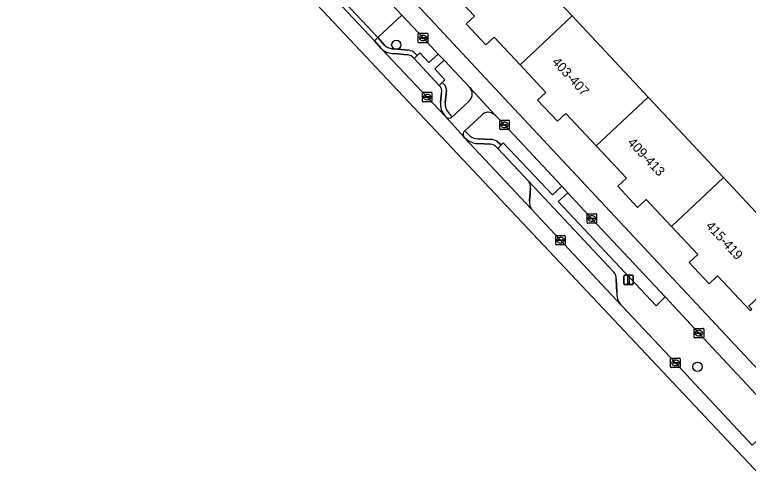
# Model space of a CAD drawing. Extents: x 163147 to 163550, y 380933 to 381639.
# Drawn here: x 163228.3 to 163305.4, y 381059.3 to 381108.1 of the extents above; entities that cross this region are included whole.
import ezdxf

# ---------------------------------------------------------------- set-up
doc = ezdxf.new("R2010")
doc.units = 0
for name, color, linetype in [('IMGEO_Berm_groen', 7, 'Continuous'), ('IMGEO_Berm_open', 7, 'Continuous'), ('IMGEO_Boom', 7, 'Continuous'), ('IMGEO_Erf', 7, 'Continuous'), ('IMGEO_Fietspad_gesloten', 7, 'Continuous'), ('IMGEO_Kolk', 7, 'Continuous'), ('IMGEO_Lichtmast', 7, 'Continuous'), ('IMGEO_Pand', 7, 'Continuous'), ('IMGEO_Pand_nummerreeks', 7, 'Continuous'), ('IMGEO_Parkeervlak_open', 7, 'Continuous'), ('IMGEO_Rijbaan_lokaal_gesloten', 7, 'Continuous'), ('IMGEO_Rijbaan_lokaal_open', 7, 'Continuous'), ('IMGEO_Voetpad_open', 7, 'Continuous')]:
    doc.layers.add(name, color=color, linetype=linetype)

msp = doc.modelspace()

# ---------------------------------------------------------------- linework, layer by layer
at = {"layer": 'IMGEO_Berm_groen'}
for points in [[(163271.237, 381105.609), (163268.976, 381108.034), (163266.455, 381105.68), (163267.166, 381104.887)], [(163270.245, 381104.151), (163270.603, 381103.802), (163270.861, 381104.066), (163271.81, 381103.049), (163272.803, 381103.944), (163271.237, 381105.609)], [(163267.93, 381104.507), (163268.195, 381104.493), (163269.587, 381104.37)], [(163276.249, 381100.24), (163276.112, 381100.428), (163273.414, 381103.291), (163272.436, 381102.374), (163273.489, 381101.219), (163273.21, 381100.945), (163273.56, 381100.588)], [(163273.677, 381100.123), (163273.637, 381099.775), (163273.532, 381098.817)], [(163273.924, 381097.725), (163274.261, 381097.355), (163276.058, 381098.995)], [(163277.337, 381097.489), (163275.595, 381095.866), (163276.119, 381095.337)], [(163279.786, 381096.484), (163278.746, 381097.539)], [(163279.045, 381094.724), (163279.411, 381094.383), (163279.622, 381094.61), (163284.805, 381089.129), (163285.784, 381090.039), (163279.786, 381096.484)], [(163277.009, 381095.017), (163278.322, 381094.966)]]:
    msp.add_lwpolyline(points, dxfattribs=at)
msp.add_lwpolyline([(163289, 381086.592), (163286.426, 381089.355), (163285.416, 381088.445), (163295.704, 381077.473), (163296.653, 381078.396)], close=True, dxfattribs=at)
for centre, radius, start, end in [((163268.141, 381105.89), 1.399, 225.79564, 261.31449), ((163269.477, 381102.941), 1.433, 57.58938, 85.59298), ((163272.416, 381100.053), 1.263, 3.17703, 25.06934), ((163275.362, 381099.739), 1.018, 313.07706, 29.47903), ((163274.911, 381098.696), 1.384, 174.96991, 224.52376), ((163278.065, 381096.865), 0.958, 44.66922, 139.39549), ((163277.068, 381096.578), 1.562, 232.60264, 267.84521), ((163278.247, 381093.54), 1.428, 56.01455, 86.97297)]:
    msp.add_arc(centre, radius, start, end, dxfattribs=at)
at = {"layer": 'IMGEO_Berm_open'}
for points in [[(163267.166, 381104.887), (163266.455, 381105.68), (163266.09, 381105.339), (163266.816, 381104.528)], [(163269.587, 381104.37), (163268.195, 381104.493), (163267.93, 381104.507)], [(163268.16, 381103.994), (163269.524, 381103.874)], [(163270.276, 381103.467), (163270.603, 381103.802), (163270.245, 381104.151)], [(163273.56, 381100.588), (163273.21, 381100.945), (163272.901, 381100.641)], [(163273.532, 381098.817), (163273.637, 381099.775), (163273.677, 381100.123)], [(163273.143, 381099.856), (163273.032, 381098.845)], [(163274.232, 381097.329), (163274.261, 381097.355), (163273.924, 381097.725)], [(163273.501, 381097.445), (163273.604, 381097.334)], [(163276.119, 381095.337), (163275.595, 381095.866), (163275.589, 381095.861)], [(163275.466, 381095.274), (163275.582, 381095.146)], [(163278.322, 381094.966), (163277.009, 381095.017)], [(163278.97, 381094.126), (163279.071, 381094.019), (163279.411, 381094.383), (163279.045, 381094.724)], [(163276.969, 381094.518), (163278.283, 381094.467)]]:
    msp.add_lwpolyline(points, dxfattribs=at)
for centre, radius, start, end in [((163268.141, 381105.89), 1.399, 225.79564, 261.31449), ((163268.106, 381105.817), 1.824, 224.97069, 271.69134), ((163269.44, 381102.821), 1.056, 37.70291, 85.45052), ((163269.477, 381102.941), 1.433, 57.58938, 85.59298), ((163272.451, 381100.073), 0.725, 342.60834, 51.65866), ((163272.416, 381100.053), 1.263, 3.17703, 25.06934), ((163274.891, 381098.689), 1.866, 175.21281, 221.82889), ((163274.911, 381098.696), 1.384, 174.96991, 224.52376), ((163273.921, 381097.654), 0.45, 225.34455, 313.74311), ((163275.842, 381095.502), 0.44, 125.18331, 211.14762), ((163277.068, 381096.578), 1.562, 232.60264, 267.84521), ((163277.063, 381096.572), 2.056, 223.91049, 267.36978), ((163278.247, 381093.54), 1.428, 56.01455, 86.97297), ((163278.253, 381093.544), 0.923, 39.0617, 88.14228)]:
    msp.add_arc(centre, radius, start, end, dxfattribs=at)
at = {"layer": 'IMGEO_Boom'}
for centre in [(163268.394, 381104.913), (163300.068, 381071.051)]:
    msp.add_circle(centre, 0.489, dxfattribs=at)
at = {"layer": 'IMGEO_Erf'}
msp.add_lwpolyline([(163327.566, 381099.224), (163294.213, 381134.916), (163292.456, 381133.038), (163277.888, 381117.465), (163278.299, 381116.877), (163278.43, 381116.999), (163281.846, 381113.348), (163286.891, 381107.954), (163294.88, 381099.413), (163302.803, 381090.943), (163307.632, 381085.78)], dxfattribs=at)
at = {"layer": 'IMGEO_Fietspad_gesloten'}
for points in [[(163431.634, 380936.983), (163426.381, 380942.59), (163389.734, 380981.756), (163386.168, 380985.564), (163372.648, 381000), (163319.829, 381056.397), (163310.14, 381066.773), (163306.558, 381070.608), (163278.278, 381100.892), (163188.415, 381197.241)], [(163236.873, 381142.447), (163243.701, 381135.131), (163244.35, 381134.436), (163254.641, 381123.403), (163255.277, 381122.722), (163262.153, 381115.349), (163268.976, 381108.034), (163271.237, 381105.609), (163272.803, 381103.944), (163273.414, 381103.291), (163276.112, 381100.428), (163276.249, 381100.24), (163278.746, 381097.539), (163279.786, 381096.484), (163285.784, 381090.039), (163286.426, 381089.355), (163289, 381086.592), (163296.653, 381078.396), (163300.254, 381074.541), (163308.689, 381065.5)]]:
    msp.add_lwpolyline(points, dxfattribs=at)
at = {"layer": 'IMGEO_Kolk'}
for p, q in [((163270.785, 381106.135), (163271.637, 381106.135)), ((163270.71, 381105.209), (163270.71, 381106.061)), ((163270.969, 381105.629), (163270.969, 381105.641)), ((163271.407, 381105.592), (163271.009, 381105.592)), ((163271.012, 381105.678), (163271.41, 381105.678)), ((163271.221, 381105.355), (163271.196, 381105.355)), ((163271.198, 381105.915), (163271.223, 381105.915)), ((163271.453, 381105.641), (163271.453, 381105.629)), ((163271.711, 381106.061), (163271.711, 381105.209)), ((163271.637, 381105.135), (163270.785, 381105.135)), ((163271.218, 381099.923), (163272.07, 381099.923)), ((163271.143, 381098.997), (163271.143, 381099.849)), ((163271.402, 381099.417), (163271.402, 381099.429)), ((163271.84, 381099.38), (163271.442, 381099.38)), ((163271.445, 381099.466), (163271.843, 381099.466)), ((163271.631, 381099.703), (163271.656, 381099.703)), ((163271.886, 381099.429), (163271.886, 381099.417)), ((163272.144, 381099.849), (163272.144, 381098.997)), ((163272.07, 381098.923), (163271.218, 381098.923)), ((163271.654, 381099.143), (163271.629, 381099.143)), ((163279.275, 381096.066), (163279.275, 381096.918)), ((163279.35, 381096.992), (163280.202, 381096.992)), ((163280.276, 381096.918), (163280.276, 381096.066)), ((163279.534, 381096.486), (163279.534, 381096.498)), ((163279.972, 381096.449), (163279.574, 381096.449)), ((163279.577, 381096.535), (163279.975, 381096.535)), ((163279.786, 381096.212), (163279.761, 381096.212)), ((163279.763, 381096.772), (163279.788, 381096.772)), ((163280.018, 381096.498), (163280.018, 381096.486)), ((163280.202, 381095.992), (163279.35, 381095.992)), ((163288.451, 381086.215), (163288.451, 381087.067)), ((163288.526, 381087.141), (163289.378, 381087.141)), ((163288.939, 381086.921), (163288.964, 381086.921)), ((163289.452, 381087.067), (163289.452, 381086.215)), ((163289.378, 381086.141), (163288.526, 381086.141)), ((163288.71, 381086.635), (163288.71, 381086.647)), ((163289.148, 381086.598), (163288.75, 381086.598)), ((163288.753, 381086.684), (163289.151, 381086.684)), ((163288.962, 381086.361), (163288.937, 381086.361)), ((163289.194, 381086.647), (163289.194, 381086.635)), ((163285.157, 381083.941), (163285.157, 381084.793)), ((163285.232, 381084.867), (163286.084, 381084.867)), ((163285.645, 381084.647), (163285.67, 381084.647)), ((163286.158, 381084.793), (163286.158, 381083.941)), ((163286.084, 381083.867), (163285.232, 381083.867)), ((163285.416, 381084.361), (163285.416, 381084.373)), ((163285.854, 381084.324), (163285.456, 381084.324)), ((163285.459, 381084.41), (163285.857, 381084.41)), ((163285.668, 381084.087), (163285.643, 381084.087)), ((163285.9, 381084.373), (163285.9, 381084.361)), ((163299.711, 381074.158), (163299.711, 381075.01)), ((163299.786, 381075.084), (163300.638, 381075.084)), ((163299.97, 381074.578), (163299.97, 381074.59)), ((163300.408, 381074.541), (163300.01, 381074.541)), ((163300.013, 381074.627), (163300.411, 381074.627)), ((163300.199, 381074.864), (163300.224, 381074.864)), ((163300.454, 381074.59), (163300.454, 381074.578)), ((163300.712, 381075.01), (163300.712, 381074.158)), ((163300.638, 381074.084), (163299.786, 381074.084)), ((163300.222, 381074.304), (163300.197, 381074.304)), ((163297.236, 381071.035), (163297.236, 381071.887)), ((163297.311, 381071.961), (163298.163, 381071.961)), ((163297.495, 381071.455), (163297.495, 381071.467)), ((163297.933, 381071.418), (163297.535, 381071.418)), ((163297.538, 381071.504), (163297.936, 381071.504)), ((163297.724, 381071.741), (163297.749, 381071.741)), ((163297.979, 381071.467), (163297.979, 381071.455)), ((163298.237, 381071.887), (163298.237, 381071.035)), ((163298.163, 381070.961), (163297.311, 381070.961)), ((163297.747, 381071.181), (163297.722, 381071.181))]:
    msp.add_line(p, q, dxfattribs=at)
for points in [[(163270.785, 381106.135), (163271.637, 381106.135)], [(163270.71, 381105.209), (163270.71, 381106.061)], [(163271.711, 381106.061), (163271.711, 381105.209)], [(163271.637, 381105.135), (163270.785, 381105.135)], [(163271.218, 381099.923), (163272.07, 381099.923)], [(163271.143, 381098.997), (163271.143, 381099.849)], [(163272.144, 381099.849), (163272.144, 381098.997)], [(163272.07, 381098.923), (163271.218, 381098.923)], [(163279.275, 381096.066), (163279.275, 381096.918)], [(163279.35, 381096.992), (163280.202, 381096.992)], [(163280.276, 381096.918), (163280.276, 381096.066)], [(163280.202, 381095.992), (163279.35, 381095.992)], [(163288.451, 381086.215), (163288.451, 381087.067)], [(163288.526, 381087.141), (163289.378, 381087.141)], [(163289.452, 381087.067), (163289.452, 381086.215)], [(163289.378, 381086.141), (163288.526, 381086.141)], [(163285.157, 381083.941), (163285.157, 381084.793)], [(163285.232, 381084.867), (163286.084, 381084.867)], [(163286.158, 381084.793), (163286.158, 381083.941)], [(163286.084, 381083.867), (163285.232, 381083.867)], [(163299.711, 381074.158), (163299.711, 381075.01)], [(163299.786, 381075.084), (163300.638, 381075.084)], [(163300.712, 381075.01), (163300.712, 381074.158)], [(163300.638, 381074.084), (163299.786, 381074.084)], [(163297.236, 381071.035), (163297.236, 381071.887)], [(163297.311, 381071.961), (163298.163, 381071.961)], [(163298.237, 381071.887), (163298.237, 381071.035)], [(163298.163, 381070.961), (163297.311, 381070.961)]]:
    msp.add_lwpolyline(points, dxfattribs=at)
for centre, radius, start, end in [((163270.787, 381106.059), 0.0765, 91.55205, 178.44795), ((163270.787, 381106.059), 0.0765, 91.55205, 178.44795), ((163271.635, 381106.059), 0.0765, 1.55205, 88.44795), ((163271.635, 381106.059), 0.0765, 1.55205, 88.44795), ((163271.009, 381105.638), 0.0403, 85.87752, 175.75265), ((163271.006, 381105.628), 0.0366, 178.93798, 274.71019), ((163271.41, 381105.635), 0.043, 264.86636, 352.45326), ((163271.414, 381105.64), 0.0386, 1.73085, 96.63898), ((163270.787, 381105.211), 0.0765, 181.55205, 268.44795), ((163270.787, 381105.211), 0.0765, 181.55205, 268.44795), ((163271.635, 381105.211), 0.0765, 271.55205, 358.44795), ((163271.635, 381105.211), 0.0765, 271.55205, 358.44795), ((163271.22, 381099.847), 0.0765, 91.55205, 178.44795), ((163271.22, 381099.847), 0.0765, 91.55205, 178.44795), ((163272.068, 381099.847), 0.0765, 1.55205, 88.44795), ((163272.068, 381099.847), 0.0765, 1.55205, 88.44795), ((163271.442, 381099.426), 0.0403, 85.87752, 175.75265), ((163271.439, 381099.416), 0.0366, 178.93798, 274.71019), ((163271.843, 381099.423), 0.043, 264.86636, 352.45326), ((163271.847, 381099.428), 0.0386, 1.73085, 96.63898), ((163271.22, 381098.999), 0.0765, 181.55205, 268.44795), ((163271.22, 381098.999), 0.0765, 181.55205, 268.44795), ((163272.068, 381098.999), 0.0765, 271.55205, 358.44795), ((163272.068, 381098.999), 0.0765, 271.55205, 358.44795), ((163279.352, 381096.916), 0.0765, 91.55205, 178.44795), ((163279.352, 381096.916), 0.0765, 91.55205, 178.44795), ((163280.2, 381096.916), 0.0765, 1.55205, 88.44795), ((163280.2, 381096.916), 0.0765, 1.55205, 88.44795), ((163279.352, 381096.068), 0.0765, 181.55205, 268.44795), ((163279.352, 381096.068), 0.0765, 181.55205, 268.44795), ((163279.574, 381096.495), 0.0403, 85.87752, 175.75265), ((163279.571, 381096.485), 0.0366, 178.93798, 274.71019), ((163279.975, 381096.492), 0.043, 264.86636, 352.45326), ((163279.979, 381096.497), 0.0386, 1.73085, 96.63898), ((163280.2, 381096.068), 0.0765, 271.55205, 358.44795), ((163280.2, 381096.068), 0.0765, 271.55205, 358.44795), ((163288.528, 381087.065), 0.0765, 91.55205, 178.44795), ((163288.528, 381087.065), 0.0765, 91.55205, 178.44795), ((163289.376, 381087.065), 0.0765, 1.55205, 88.44795), ((163289.376, 381087.065), 0.0765, 1.55205, 88.44795), ((163288.528, 381086.217), 0.0765, 181.55205, 268.44795), ((163288.528, 381086.217), 0.0765, 181.55205, 268.44795), ((163288.75, 381086.644), 0.0403, 85.87752, 175.75265), ((163288.747, 381086.634), 0.0366, 178.93798, 274.71019), ((163289.151, 381086.641), 0.043, 264.86636, 352.45326), ((163289.155, 381086.646), 0.0386, 1.73085, 96.63898), ((163289.376, 381086.217), 0.0765, 271.55205, 358.44795), ((163289.376, 381086.217), 0.0765, 271.55205, 358.44795), ((163285.234, 381084.791), 0.0765, 91.55205, 178.44795), ((163285.234, 381084.791), 0.0765, 91.55205, 178.44795), ((163286.082, 381084.791), 0.0765, 1.55205, 88.44795), ((163286.082, 381084.791), 0.0765, 1.55205, 88.44795), ((163285.234, 381083.943), 0.0765, 181.55205, 268.44795), ((163285.234, 381083.943), 0.0765, 181.55205, 268.44795), ((163285.456, 381084.37), 0.0403, 85.87752, 175.75265), ((163285.453, 381084.36), 0.0366, 178.93798, 274.71019), ((163285.857, 381084.367), 0.043, 264.86636, 352.45326), ((163285.861, 381084.372), 0.0386, 1.73085, 96.63898), ((163286.082, 381083.943), 0.0765, 271.55205, 358.44795), ((163286.082, 381083.943), 0.0765, 271.55205, 358.44795), ((163299.788, 381075.008), 0.0765, 91.55205, 178.44795), ((163299.788, 381075.008), 0.0765, 91.55205, 178.44795), ((163300.01, 381074.587), 0.0403, 85.87752, 175.75265), ((163300.007, 381074.577), 0.0366, 178.93798, 274.71019), ((163300.411, 381074.584), 0.043, 264.86636, 352.45326), ((163300.415, 381074.589), 0.0386, 1.73085, 96.63898), ((163300.636, 381075.008), 0.0765, 1.55205, 88.44795), ((163300.636, 381075.008), 0.0765, 1.55205, 88.44795), ((163299.788, 381074.16), 0.0765, 181.55205, 268.44795), ((163299.788, 381074.16), 0.0765, 181.55205, 268.44795), ((163300.636, 381074.16), 0.0765, 271.55205, 358.44795), ((163300.636, 381074.16), 0.0765, 271.55205, 358.44795), ((163297.313, 381071.885), 0.0765, 91.55205, 178.44795), ((163297.313, 381071.885), 0.0765, 91.55205, 178.44795), ((163297.535, 381071.464), 0.0403, 85.87752, 175.75265), ((163297.532, 381071.454), 0.0366, 178.93798, 274.71019), ((163297.936, 381071.461), 0.043, 264.86636, 352.45326), ((163297.94, 381071.466), 0.0386, 1.73085, 96.63898), ((163298.161, 381071.885), 0.0765, 1.55205, 88.44795), ((163298.161, 381071.885), 0.0765, 1.55205, 88.44795), ((163297.313, 381071.037), 0.0765, 181.55205, 268.44795), ((163297.313, 381071.037), 0.0765, 181.55205, 268.44795), ((163298.161, 381071.037), 0.0765, 271.55205, 358.44795), ((163298.161, 381071.037), 0.0765, 271.55205, 358.44795)]:
    msp.add_arc(centre, radius, start, end, dxfattribs=at)
for centre, major_axis, ratio, start_param, end_param in [((163271.197, 381105.635), (-0.387, 0.002), 0.722429, 4.712389, 7.853982), ((163271.222, 381105.635), (-0.39, 0.002), 0.717154, 1.570796, 4.712389), ((163271.63, 381099.423), (-0.387, 0.002), 0.722429, 4.712389, 7.853982), ((163271.655, 381099.423), (-0.39, 0.002), 0.717154, 1.570796, 4.712389), ((163279.762, 381096.492), (-0.387, 0.002), 0.722429, 4.712389, 7.853982), ((163279.787, 381096.492), (-0.39, 0.002), 0.717154, 1.570796, 4.712389), ((163288.938, 381086.641), (-0.387, 0.002), 0.722429, 4.712389, 7.853982), ((163288.963, 381086.641), (-0.39, 0.002), 0.717154, 1.570796, 4.712389), ((163285.644, 381084.367), (-0.387, 0.002), 0.722429, 4.712389, 7.853982), ((163285.669, 381084.367), (-0.39, 0.002), 0.717154, 1.570796, 4.712389), ((163300.198, 381074.584), (-0.387, 0.002), 0.722429, 4.712389, 7.853982), ((163300.223, 381074.584), (-0.39, 0.002), 0.717154, 1.570796, 4.712389), ((163297.723, 381071.461), (-0.387, 0.002), 0.722429, 4.712389, 7.853982), ((163297.748, 381071.461), (-0.39, 0.002), 0.717154, 1.570796, 4.712389)]:
    msp.add_ellipse(centre, major_axis=major_axis, ratio=ratio, start_param=start_param, end_param=end_param, dxfattribs=at)
at = {"layer": 'IMGEO_Lichtmast'}
for p, q in [((163292.421, 381080.688), (163293.211, 381080.688)), ((163293.211, 381080.688), (163292.421, 381080.688)), ((163292.321, 381079.788), (163292.321, 381080.588)), ((163292.321, 381080.588), (163292.321, 381079.788)), ((163293.311, 381080.588), (163293.311, 381079.788)), ((163293.311, 381079.788), (163293.311, 381080.588)), ((163293.211, 381079.688), (163292.421, 381079.688)), ((163292.421, 381079.688), (163293.211, 381079.688))]:
    msp.add_line(p, q, dxfattribs=at)
msp.add_lwpolyline([(163292.741, 381080.563), (163292.891, 381080.563), (163292.891, 381079.813), (163292.741, 381079.813), (163292.741, 381080.563)], dxfattribs=at)
for centre, start, end in [((163292.421, 381080.588), 90, 180), ((163292.421, 381080.588), 90, 180), ((163293.211, 381080.588), 0, 90), ((163293.211, 381080.588), 360, 90), ((163292.421, 381079.788), 180, 270), ((163292.421, 381079.788), 180, 270), ((163293.211, 381079.788), 270, 0), ((163293.211, 381079.788), 270, 0)]:
    msp.add_arc(centre, 0.1, start, end, dxfattribs=at)
at = {"layer": 'IMGEO_Pand'}
for points in [[(163281.406, 381102.825), (163286.891, 381107.954), (163281.846, 381113.348), (163278.43, 381116.999), (163278.299, 381116.877), (163278.155, 381116.742), (163278.334, 381116.55), (163276.202, 381114.555), (163275.941, 381114.835), (163275.132, 381114.079), (163275.389, 381113.804), (163273.312, 381111.86), (163273.062, 381112.128), (163272.859, 381111.938), (163276.601, 381107.937), (163275.724, 381107.117), (163277.793, 381104.905), (163278.683, 381105.737)], [(163294.88, 381099.413), (163286.891, 381107.954), (163281.406, 381102.825), (163284.13, 381099.913), (163283.255, 381099.095), (163285.338, 381096.869), (163286.218, 381097.692), (163289.402, 381094.288)], [(163297.319, 381085.815), (163302.803, 381090.943), (163294.88, 381099.413), (163289.402, 381094.288), (163292.586, 381090.885), (163291.673, 381090.03), (163293.754, 381087.806), (163294.662, 381088.655)], [(163297.319, 381085.815), (163300.089, 381082.853), (163299.198, 381082.019), (163301.286, 381079.786), (163302.167, 381080.61), (163305.592, 381076.949), (163305.767, 381077.113), (163305.465, 381077.436), (163307.591, 381079.425), (163307.821, 381079.179), (163308.588, 381079.896), (163308.363, 381080.136), (163310.55, 381082.181), (163310.809, 381081.904), (163311.048, 381082.128), (163310.741, 381082.456), (163307.632, 381085.78), (163302.803, 381090.943)]]:
    msp.add_lwpolyline(points, close=True, dxfattribs=at)
at = {"layer": 'IMGEO_Parkeervlak_open'}
for points in [[(163266.816, 381104.528), (163273.501, 381097.445)], [(163269.524, 381103.874), (163268.16, 381103.994)], [(163272.901, 381100.641), (163270.276, 381103.467)], [(163273.032, 381098.845), (163273.143, 381099.856)], [(163275.582, 381095.146), (163282.56, 381087.679)], [(163278.283, 381094.467), (163276.969, 381094.518)], [(163279.071, 381094.019), (163278.97, 381094.126)], [(163282.325, 381090.547), (163279.071, 381094.019)], [(163291.282, 381080.99), (163282.325, 381090.547)], [(163282.52, 381089.792), (163282.393, 381088.49)], [(163282.393, 381088.49), (163282.52, 381089.792)], [(163282.56, 381087.679), (163292.004, 381077.575)], [(163291.567, 381078.881), (163291.528, 381080.259)]]:
    msp.add_lwpolyline(points, dxfattribs=at)
for centre, radius, start, end in [((163268.106, 381105.817), 1.824, 224.97069, 271.69134), ((163269.44, 381102.821), 1.056, 37.70291, 85.45052), ((163272.451, 381100.073), 0.725, 342.60834, 51.65866), ((163274.891, 381098.689), 1.866, 175.21281, 221.82889), ((163277.063, 381096.572), 2.056, 223.91049, 267.36978), ((163278.253, 381093.544), 0.923, 39.0617, 88.14228), ((163281.274, 381089.873), 1.248, 356.28272, 32.68082), ((163281.274, 381089.873), 1.248, 356.28272, 32.68082), ((163283.851, 381088.368), 1.463, 175.20143, 208.06983), ((163283.851, 381088.368), 1.463, 175.20143, 208.06983), ((163290.473, 381080.311), 1.057, 357.19253, 40.00625), ((163293.434, 381078.78), 1.87, 176.89459, 220.10687)]:
    msp.add_arc(centre, radius, start, end, dxfattribs=at)
at = {"layer": 'IMGEO_Rijbaan_lokaal_gesloten'}
for points in [[(163224.239, 381147.157), (163352.566, 381010.865)], [(163305.819, 381062.795), (163299.374, 381069.695), (163297.748, 381071.447), (163292.133, 381077.437), (163292.004, 381077.575), (163282.56, 381087.679), (163275.582, 381095.146), (163275.466, 381095.274), (163273.604, 381097.334), (163273.501, 381097.445), (163266.816, 381104.528), (163266.09, 381105.339), (163259.301, 381112.6), (163257.862, 381114.198), (163229.126, 381144.967)]]:
    msp.add_lwpolyline(points, dxfattribs=at)
at = {"layer": 'IMGEO_Rijbaan_lokaal_open'}
msp.add_lwpolyline([(163268.976, 381108.034), (163262.153, 381115.349), (163259.661, 381112.947), (163266.455, 381105.68)], close=True, dxfattribs=at)
at = {"layer": 'IMGEO_Voetpad_open'}
for points in [[(163188.415, 381197.241), (163278.278, 381100.892), (163306.558, 381070.608)], [(163305.592, 381076.949), (163302.167, 381080.61), (163301.286, 381079.786), (163299.198, 381082.019), (163300.089, 381082.853), (163297.319, 381085.815), (163294.662, 381088.655), (163293.754, 381087.806), (163291.673, 381090.03), (163292.586, 381090.885), (163289.402, 381094.288), (163286.218, 381097.692), (163285.338, 381096.869), (163283.255, 381099.095), (163284.13, 381099.913), (163281.406, 381102.825), (163278.683, 381105.737), (163277.793, 381104.905), (163275.724, 381107.117), (163276.601, 381107.937), (163272.859, 381111.938)], [(163278.746, 381097.539), (163276.249, 381100.24)], [(163276.058, 381098.995), (163274.261, 381097.355), (163274.232, 381097.329)], [(163273.604, 381097.334), (163275.466, 381095.274)], [(163275.589, 381095.861), (163275.595, 381095.866), (163277.337, 381097.489)], [(163285.416, 381088.445), (163286.426, 381089.355), (163285.784, 381090.039), (163284.805, 381089.129), (163279.622, 381094.61), (163279.411, 381094.383), (163279.071, 381094.019), (163282.325, 381090.547), (163291.282, 381080.99)], [(163292.004, 381077.575), (163292.133, 381077.437), (163297.748, 381071.447), (163299.374, 381069.695), (163305.819, 381062.795), (163306.184, 381063.136), (163308.689, 381065.5), (163300.254, 381074.541), (163296.653, 381078.396), (163295.704, 381077.473), (163285.416, 381088.445)], [(163291.528, 381080.259), (163291.567, 381078.881)]]:
    msp.add_lwpolyline(points, dxfattribs=at)
for points in [[(163266.455, 381105.68), (163259.661, 381112.947), (163259.301, 381112.6), (163266.09, 381105.339)], [(163273.414, 381103.291), (163272.803, 381103.944), (163271.81, 381103.049), (163270.861, 381104.066), (163270.603, 381103.802), (163270.276, 381103.467), (163272.901, 381100.641), (163273.21, 381100.945), (163273.489, 381101.219), (163272.436, 381102.374)]]:
    msp.add_lwpolyline(points, close=True, dxfattribs=at)
for centre, radius, start, end in [((163275.362, 381099.739), 1.018, 313.07706, 29.47903), ((163278.065, 381096.865), 0.958, 44.66922, 139.39549), ((163273.921, 381097.654), 0.45, 225.34455, 313.74311), ((163275.842, 381095.502), 0.44, 125.18331, 211.14762), ((163290.473, 381080.311), 1.057, 357.19253, 40.00625), ((163293.434, 381078.78), 1.87, 176.89459, 220.10687)]:
    msp.add_arc(centre, radius, start, end, dxfattribs=at)

# ---------------------------------------------------------------- texts
at = {"layer": 'IMGEO_Pand_nummerreeks'}
for s, rotation, p in [('403-407', 312.76883, (163284.693, 381103.057)), ('409-413', 313.43778, (163292.636, 381094.574)), ('415-419', 312.66798, (163300.871, 381085.811))]:
    msp.add_text(s, height=1, rotation=rotation, dxfattribs=at).set_placement(p)

doc.saveas('drawing.dxf')
